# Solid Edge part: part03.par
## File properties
Author: Administrator
Template: normal.par
Last saved by: Ashutosh-CADCIM
Revision: 16
Application: Solid Edge
Accuracy: 0.99
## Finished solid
Body 1: solid body, 54 faces, 136 edges, 72 vertices.
  Faces by surface: cylinder 40, plane 14
  Edges by curve: circle 74, line 50, ellipse 12
Bounding box of the edges (mm): 320.500 x 112.000 x 70.000, from (-118.4884, -56, -35) to (202.0116, 56, 35).
Cylindrical faces by radius (mm): R5 x8, R6 x2, R12 x1, R13 x8, R17.5 x1, R26 x1, R31.5 x3, R35 x2, R72.03 x8, R78 x4, R207.0766 x1, R207.2725 x1
Planar faces by outward normal: +y 1, +z 4, -y 1, -z 4, oblique 4
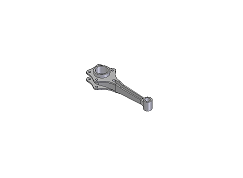
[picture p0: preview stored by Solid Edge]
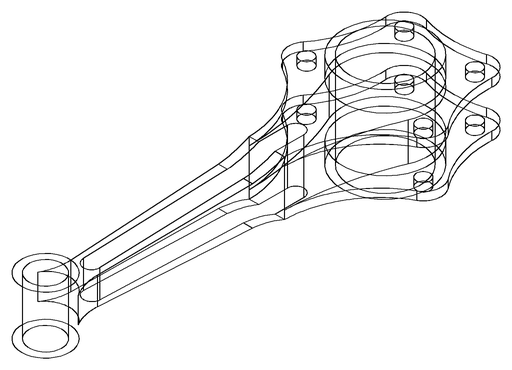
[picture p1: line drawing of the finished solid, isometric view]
